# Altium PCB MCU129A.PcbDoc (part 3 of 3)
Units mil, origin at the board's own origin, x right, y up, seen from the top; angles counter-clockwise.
Board outline 3092.79 x 1702.62 mil, 4 copper layers (Top Layer, L2_GND, L3_PWR/SIG, Bottom Layer), stack 58.736 mil thick; 213 components, 108 nets, 914 pads, 219 vias.
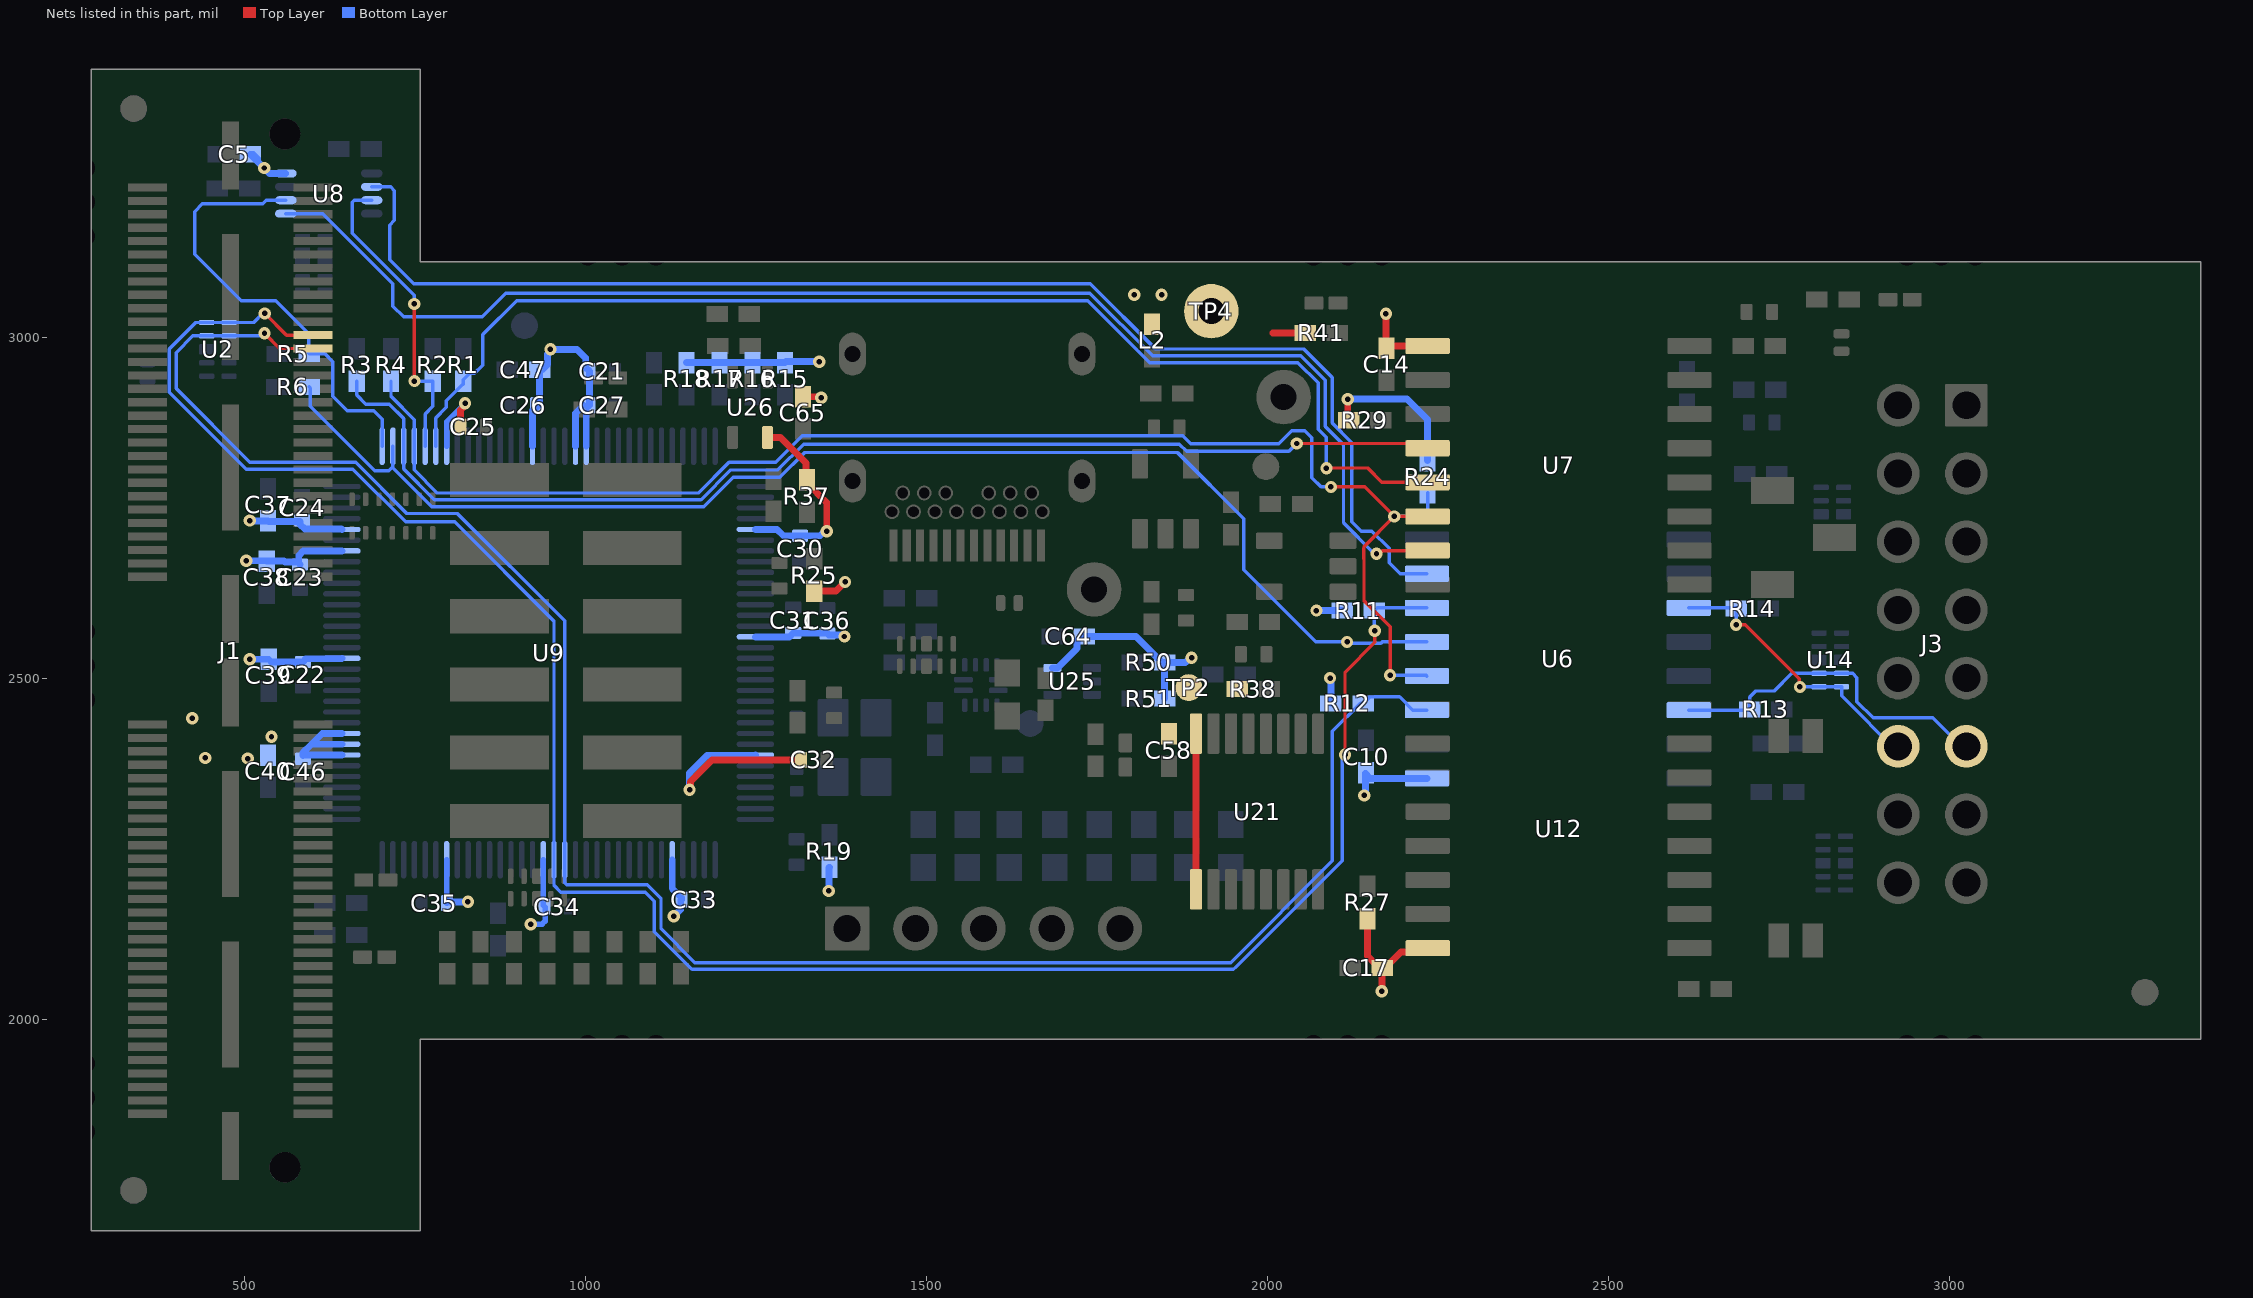
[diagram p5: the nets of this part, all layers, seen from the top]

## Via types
v1: diameter 18, hole 8, Top Layer to Bottom Layer, tented both sides, 219 vias

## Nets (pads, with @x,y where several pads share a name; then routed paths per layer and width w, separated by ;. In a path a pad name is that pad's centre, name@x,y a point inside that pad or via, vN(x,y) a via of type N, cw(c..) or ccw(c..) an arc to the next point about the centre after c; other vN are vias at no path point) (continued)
VCC_3V3: C5.2 C10.1 C14.1 C17.1 C21.2 C22.2 C23.2 C24.2 C25.2 C26.2 C27.2 C30.2 C31.2 C32.2 C33.2 C34.2 C35.2 C36.2 C37.1 C38.1 C39.1 C40.1 C46.2 C47.1 C64.2 C65.2 L2.2 R11.2 R12.2 R15.1 R16.1 R17.1 R18.1 R19.1 R24.2 R25.2 R27.2 R29.2 R37.2 R41.2 R50.2 R51.2 TP4.1 U6.1 U7.1 U8.8 U9.7 U9.8 U9.9 U9.16 U9.26 U9.28 U9.39 U9.47 U9.51 U9.52 U9.69 U9.79 U9.90 U9.101 U9.113 U9.122 U12.16 U25.5 U26.5 | length 3662.8
  Top Layer w10: C25.2@817.13,2869.83 817.13,2894.05 823.61,2900.53 v1(823.61,2904.05) ; v1(1152.82,2337.6) 1154.35,2339.13 1154.35,2349.79 1185.74,2381.18 C32.2@1315.19,2381.18 ; U26.5@1267.02,2854.08 1285.91,2854.08 1323.42,2816.57 1323.42,2793.06 R37.2@1324.81,2791.68 ; C65.2@1318.81,2913.8 1344.19,2913.8 v1(1345.81,2912.18) ; R37.2@1325.3,2787.24 1353.81,2758.74 v1(1353.81,2716.35) ; R25.2@1335.62,2628.69 1367.31,2628.69 v1(1380.81,2642.18) ; 2007.81,3007.18 R41.2@2055.19,3007.18 ; v1(2117.81,2910.18) 2117.81,2880.56 R29.2@2119.19,2879.18 ; R27.2@2146.81,2148.56 2146.81,2093.87 2164.49,2076.18 C17.1@2172.37,2076.18 ; v1(2167.81,2042.18) 2167.81,2075.56 2171.75,2075.56 2195.99,2099.8 2229.57,2099.8 U12.16@2234.94,2105.18 ; v1(2173.81,3035.18) 2173.81,2985.8 2176.19,2988.18 U7.1@2234.88,2988.18
  Bottom Layer w5: 997.25,2901.18 1005.34,2901.18 C27.2@1006.11,2901.18
  Bottom Layer w8: C35.2@796.57,2172.42 U9.122@796.57,2234.88 ; U9.39@796.57,2841.18 796.57,2877.01 v1(823.61,2904.05) ; v1(919.96,2140.3) 936.5,2140.3 941.19,2144.98 C34.2@941.19,2165.18 ; C34.2@938.3,2168.06 U9.113@938.3,2234.88
  Bottom Layer w10: v1(502.81,2673.18) 532.43,2673.18 C38.1@532.81,2672.8 558.19,2672.8 559.81,2671.18 578.26,2671.18 C23.2@579.81,2669.64 ; v1@507.47,2528.18 v1(508.09,2528.8) C39.1@535.81,2528.8 539.73,2524.88 C22.2@585.81,2524.88 590.53,2529.61 642.48,2529.61 U9.16@643.03,2530.16 ; v1(508.09,2732.18) 508.71,2731.56 C37.1@534.81,2731.56 535.81,2730.56 581.81,2730.56 581.81,2726.62 588.62,2719.81 642.35,2719.81 U9.28@643.03,2719.13 ; v1(529.32,3249.06) v1@528.93,3249.06 ; U8.8@560.82,3241.18 536.81,3241.18 v1@528.93,3249.06 ; C23.2@581.81,2667.64 C23.2@579.81,2669.64 ; U9.7@643.03,2388.43 586.67,2388.43 586.05,2387.81 586.05,2391.75 598.48,2404.17 ; U9.8@643.03,2404.17 598.48,2404.17 ; U9.9@643.03,2419.92 614.23,2419.92 598.48,2404.17 ; U9.26@643.03,2687.64 586.26,2687.64 579.81,2681.18 C23.2@579.81,2669.64 ; C35.2@796.57,2172.42 796.81,2172.18 797.81,2173.18 798.31,2172.68 827.31,2172.68 v1(827.81,2173.18) ; U9.47@922.56,2841.18 922.56,2893.37 930.37,2901.18 932.81,2901.18 C47.1@932.81,2953.18 936.75,2953.18 944.56,2960.99 944.56,2976.22 948.81,2980.48 v1(948.81,2983.18) 987.81,2983.18 1000.5,2970.49 1000.5,2956.79 C21.2@1006.11,2951.18 C27.2@1006.11,2901.18 ; U9.51@985.55,2841.18 985.55,2889.48 997.25,2901.18 ; U9.52@1001.3,2841.18 1001.3,2897.13 C27.2@1005.34,2901.18 ; U9.101@1127.28,2234.88 1127.28,2192.96 1141.11,2179.13 C33.2@1141.11,2176.18 1139.81,2174.88 1139.81,2162.1 v1(1129.75,2152.04) ; R18.1@1148.46,2963.8 R17.1@1196.81,2963.8 R16.1@1244.81,2963.8 R15.1@1292.81,2963.8 1294.19,2965.18 v1(1342.81,2965.18) ; v1(1152.82,2337.6) 1152.82,2362.19 1178.24,2387.61 1248.52,2387.61 U9.90@1249.33,2388.43 ; U9.79@1249.33,2561.65 1298.98,2561.65 C31.2@1304.81,2567.48 1305.31,2566.98 1354.31,2566.98 C36.2@1354.81,2566.48 1356.96,2564.33 1377.66,2564.33 v1(1379.81,2562.18) ; U9.69@1249.33,2719.13 1281.18,2719.13 1290.43,2709.88 C30.2@1314.81,2709.88 1343.83,2709.88 1350.29,2716.35 v1(1353.81,2716.35) ; v1(1356.81,2189.18) 1357.31,2189.68 1357.31,2223.44 R19.1@1357.81,2223.94 ; U25.5@1684.67,2516.08 1691.96,2516.08 1720.68,2544.8 1720.68,2555.37 1727.49,2562.18 C64.2@1731.43,2562.18 1807.37,2562.18 1845.37,2524.18 R50.2@1849.3,2524.18 ; R51.2@1849.3,2471.18 R50.2@1849.3,2524.18 ; v1(1888.81,2531.18) 1886.64,2531.18 1879.64,2524.18 R50.2@1849.3,2524.18 ; v1(2071.81,2600.18) R11.2@2109.56,2600.18 ; v1(2091.81,2501.18) 2093.19,2499.8 R12.2@2093.19,2464.18 ; v1(2117.81,2910.18) 2204.81,2910.18 2234.88,2880.11 R24.2@2234.88,2819.99 ; v1(2141.81,2329.18) 2143.81,2331.18 C10.1@2143.81,2360.99 ; C10.1@2143.81,2361.56 C10.1@2143.81,2360.99 ; U6.1@2233.88,2354.18 2150.62,2354.18 C10.1@2143.81,2360.99 ; C5.2@519.56,3258.43 C5.2@508.81,3269.18 512.75,3269.18 519.56,3262.37 C5.2@519.56,3258.43 ; C5.2@519.56,3258.43 v1@528.93,3249.06
  other v1: 504.81,2383.18 442.81,2384.18 539.81,2415.18 423.81,2442.18 1804.81,3063.18 1844.81,3063.18
VREF: C58.2 R38.1 TP2.1 U21.8 U21.9 | length 228.3
  Top Layer w10: U21.9@1895.3,2191.39 U21.8@1895.3,2419.74
XDS_EEPROM_SCL: J1.23 R11.1 U2.5 U2.6 U6.6 U9.112 | length 3163.7
  Top Layer w5: v1(529.98,3035.86) 561.79,3004.05 J1.23@600.99,3004.05 ; v1(2113.81,2388.68) 2113.81,2509.88 2157.4,2553.47 v1(2157.4,2570.66)
  Bottom Layer w5: v1(529.98,3035.86) 527.05,3035.86 513.75,3022.56 U2.6@477.69,3022.56 U2.5@444.81,3022.56 428.81,3022.56 389.98,2983.73 389.98,2920.33 502.75,2807.56 659.08,2807.56 736.42,2730.22 808.41,2730.22 954.05,2584.58 U9.112@954.05,2234.88 954.05,2197.14 963.93,2187.26 1082.57,2187.26 1082.82,2187.02 1087.7,2187.02 1100.94,2173.78 1100.94,2129.47 1153.17,2077.24 1156.31,2074.1 1950.17,2074.1 1953.31,2077.24 2109.6,2233.52 2109.6,2384.47 v1(2113.81,2388.68) ; v1(2157.4,2570.66) 2156.81,2571.24 R11.1@2156.81,2600.18 2160.81,2604.18 U6.6@2233.88,2604.18
XDS_EEPROM_SCL_ISO: J3.12 R14.1 U6.11 U14.5 U14.6 | length 423
  Top Layer w5: v1(2687.19,2579.56) 2700.72,2579.56 2779.79,2500.5 2779.79,2489.2 v1(2780.81,2488.18)
  Bottom Layer w5: U6.11@2617.74,2604.18 R14.1@2687.19,2604.18 ; v1(2687.19,2579.56) R14.1@2687.19,2603.18 ; v1(2780.81,2488.18) 2781.07,2488.44 U14.6@2808.93,2488.44 U14.5@2841.81,2488.44 2841.81,2475.04 J3.12@2924.81,2392.04
XDS_EEPROM_SDA: J1.25 R12.1 U2.4 U2.7 U6.3 U9.111 | length 2988.8
  Top Layer w5: v1(529.55,3006.81) 551.99,2984.36 J1.25@600.99,2984.36
  Bottom Layer w5: v1(529.55,3006.81) 525.61,3002.87 U2.7@477.69,3002.87 U2.4@444.81,3002.87 424.46,3002.87 399.98,2978.39 399.98,2925.76 508.18,2817.56 663.22,2817.56 738.27,2742.51 812.46,2742.51 969.8,2585.17 969.8,2200.99 972.73,2198.06 1090.8,2198.06 1110.94,2177.92 1110.94,2133.61 1160.45,2084.1 1946.03,2084.1 2095.31,2233.38 2095.31,2423 2136.49,2464.18 R12.1@2140.43,2464.18 2149.74,2473.49 2156.42,2473.49 2156.61,2473.68 2193.71,2473.68 2213.21,2454.18 U6.3@2233.88,2454.18
XDS_EEPROM_SDA_ISO: J3.11 R13.1 U6.14 U14.4 U14.7 | length 509.1
  Bottom Layer w5: U6.14@2617.74,2454.18 R13.1@2707.19,2454.18 ; R13.1@2707.19,2455.18 2707.19,2473.46 2715.99,2482.27 2742.84,2482.27 2768.7,2508.13 U14.7@2808.93,2508.13 2858.14,2508.13 2864.3,2501.97 2864.3,2466.69 2888.01,2442.98 2975.2,2442.98 J3.11@3025.65,2392.53
XDS_RXD: R5.1 U8.6 U9.33 | length 663.9
  Bottom Layer w5: 522.3,3054.34 495.53,3054.34 427.31,3122.56 427.31,3185.2 438.56,3196.45 526.93,3196.45 532.3,3201.81 U8.6@560.82,3201.81 ; 522.32,3054.36 537.64,3054.36 ; 537.66,3054.34 545.8,3054.34 594.33,3005.82 594.33,2977.4 R5.1@595.25,2976.48 618.24,2976.48 629.43,2965.29 629.43,2914.42 650.88,2892.97 689.7,2892.97 702.08,2880.59 U9.33@702.08,2841.18
XDS_RXD_BUF: U6.7 U8.2 | length 1970.6
  Bottom Layer w5: U8.2@686.81,3221.5 714.56,3221.5 720.06,3216 720.06,3172.4 712.93,3165.27 712.93,3114.61 748.39,3079.15 1740.42,3079.15 1835.89,2983.68 2053.01,2983.68 2094.77,2941.93 2094.77,2875.15 2123.78,2846.14 2123.78,2730.5 2137.67,2716.61 2153.07,2716.61 2178.42,2691.26 2178.42,2670.39 2194.64,2654.18 U6.7@2233.88,2654.18
XDS_TCK: R3.2 U7.4 U9.35 | length 1743.4
  Top Layer w5: v1(2043.11,2845.11) 2227.95,2845.11 U7.4@2234.88,2838.18
  Bottom Layer w5: R3.2@664.81,2936.69 664.81,2916.25 678.08,2902.97 712.35,2902.97 733.58,2881.74 U9.35@733.58,2841.18 ; U9.35@733.53,2841.13 733.53,2807.74 778.75,2762.51 1169.59,2762.51 1213.41,2806.33 1282.04,2806.33 1320,2844.29 1871,2844.29 1881.6,2833.7 2031.69,2833.7 2033.63,2835.64 v1(2043.11,2845.11)
XDS_TDI: R1.1 U7.5 U9.38 | length 1778.5
  Top Layer w5: v1(2086.52,2808.71) 2087.03,2809.22 2146.9,2809.22 2167.93,2788.18 U7.5@2234.88,2788.18
  Bottom Layer w5: U9.38@780.82,2841.18 780.82,2882.54 796.28,2898 796.28,2908 R1.1@819.73,2931.45 ; R1.1@821.04,2931.7 821.04,2938.65 830.35,2947.97 837.42,2947.97 849.5,2960.04 849.5,3004.94 899.1,3054.54 1736.75,3054.54 1827.61,2963.68 2044.73,2963.68 2074.31,2934.1 2074.31,2866.13 2086.44,2854 2086.44,2808.8 v1(2086.52,2808.71)
XDS_TDO: R2.1 U8.3 U9.37 | length 456.7
  Top Layer w5: v1(749.04,3049.71) 749.33,3049.42 v1(749.33,2936.69)
  Bottom Layer w5: U8.3@686.81,3201.81 661.23,3201.81 658.3,3198.88 658.3,3153.21 749.04,3062.47 v1(749.04,3049.71) ; v1(749.33,2936.69) R2.1@776.23,2936.7 776.23,2899.52 765.08,2888.36 U9.37@765.08,2841.18
XDS_TDO_BUF: U7.7 U8.5 | length 2036.4
  Top Layer w5: v1(2159.92,2683.6) 2163.44,2683.6 2168.02,2688.18 U7.7@2233.88,2688.18
  Bottom Layer w5: U8.5@560.82,3182.13 615.24,3182.13 717.83,3079.54 717.83,3046.53 733.44,3030.92 848.65,3030.92 883.33,3065.61 1739.83,3065.61 1831.75,2973.68 2048.87,2973.68 2084.55,2938 2084.55,2870.03 2111.61,2842.97 2111.61,2728.53 2156.54,2683.6 v1(2159.92,2683.6)
XDS_TMS: R4.2 R24.1 U6.4 U7.6 U9.36 | length 2178.2
  Top Layer w5: v1(2093.11,2781.49) 2142.5,2781.49 v1(2185.81,2738.18) ; v1(2179.81,2505.18) 2179.81,2576.41 2141.58,2614.64 2141.58,2675.78 2141.42,2675.94 2141.42,2691.26 2141.58,2691.42 2141.58,2693.96 v1(2185.81,2738.18) ; U7.6@2234.88,2738.18 v1(2185.81,2738.18)
  Bottom Layer w5: R4.2@715.05,2936.69 715.05,2914.42 749.33,2880.14 U9.36@749.33,2841.18 748.97,2840.82 748.97,2806.44 782.9,2772.51 1165.45,2772.51 1210.57,2817.63 1279.19,2817.63 1318,2856.43 1875.59,2856.43 1887.53,2844.49 2016.33,2844.49 2035.44,2863.61 2054.93,2863.61 2065.04,2853.5 2065.04,2794.98 2078.53,2781.49 v1(2093.11,2781.49) ; v1(2179.81,2505.18) 2232.88,2505.18 U6.4@2233.88,2504.18 ; v1(2185.81,2738.18) 2225.18,2738.18 2234.88,2747.88 R24.1@2234.88,2772.75
XDS_TXD: R6.1 U6.5 U9.34 | length 1956.5
  Bottom Layer w5: R6.1@594.96,2928.08 596.56,2926.48 596.56,2899.94 691.38,2805.12 711.59,2805.12 717.83,2811.36 U9.34@717.83,2841.18 ; 717.03,2810.56 717.03,2810.09 774.61,2752.51 1173.73,2752.51 1216.64,2795.42 1285.27,2795.42 1321.83,2831.98 1868.17,2831.98 1965.03,2735.12 1965.03,2660.17 2071.01,2554.18 v1(2116.81,2554.18) 2118.83,2552.16 2166.59,2552.16 2168.62,2554.18 U6.5@2233.88,2554.18
pads on no net: Designator1_1_2_2. Designator1_1_2_2_1. Designator1_1_2_3. Designator1_1_2_3_1. Designator1_1_2_4. Designator1_1_2_5. Designator1_1_2_5_1. Designator1_1_2_7. Designator1_1_2_7_1. Designator1_1_2_8. Designator1_1_2_8_1. Designator1_3_1_1. Designator1_3_1_1_1. Designator1_3_1_1_2. Designator2_1. Designator2_1_1. Designator3_1_2_2. Designator3_1_2_2_1. Designator3_1_2_3. Designator3_1_2_3_1. Designator3_1_2_4. Designator3_3_1_1. Designator3_3_1_1_1. Designator3_3_1_1_2. Designator4_1_2_2. Designator4_1_2_2_1. Designator4_1_2_3. Designator4_1_2_3_1. Designator4_1_2_4. Designator4_3_1_1. Designator4_3_1_1_1. Designator4_3_1_1_2. Designator5_1. Designator5_1_1. Designator6_1. Designator6_1_1. FID1.1 FID2.1 FID3.1 FID5.1 FID6.1 FID7.1 FID8.1 FID9.1 FID10.1 FID11.1 FID12.1 FID13.1 FID14.1 FID15.1 J1.1 J1.2 J1.3 J1.4 J1.6 J1.8 J1.10 J1.12 J1.14 J1.16 J1.27 J1.29 J1.30 J1.32 J1.34 J1.35 J1.36 J1.37 J1.38 J1.39 J1.40 J1.41 J1.42 J1.43 J1.44 J1.45 J1.46 J1.47 J1.48 J1.49 J1.50 J1.51 J1.52 J1.53 J1.54 J1.55 J1.56 J1.57 J1.58 J1.59 J1.60 J1.61 J1.62 J1.63 J1.64 J1.65 J1.66 J1.67 J1.68 J1.69 J1.70 J1.71 J1.72 J1.73 J1.74 J1.75 J1.76 J1.79 J1.80 J1.81 J1.82 J1.83 J1.84 J1.85 J1.86 J1.87 J1.88 J1.89 J1.90 J1.91 J1.92 J1.93 J1.94 J1.95 J1.96 J1.97 J1.98 J1.99 J1.100 J1.101 J1.102 J1.103 J1.104 J1.105 J1.106 J1.107 J1.108 J1.109 J1.110 J1.111 J1.112 J1.113 J1.114 J1.115 J1.116 J1.MH1 J1.MH2 J3.8 J5.A2 J5.A3 J5.A8 J5.A10 J5.A11 J5.B2 J5.B3 J5.B8 J5.B10 J5.B11 LBL1.0 U1.3@585.43,3109.19 U1.8@618.31,3109.19 U2.3@444.81,2983.19 U2.8@477.69,2983.19 U3.1S U3.2S U4.3@929.81,2210.62 U4.8@929.81,2177.74 U9.1 U9.2 U9.5 U9.6 U9.11 U9.12 U9.13 U9.14 U9.15 U9.18 U9.19 U9.20 U9.21 U9.22 U9.23 U9.24 U9.25 U9.27 U9.29 U9.30 U9.31 U9.32 U9.41 U9.42 U9.43 U9.44 U9.45 U9.46 U9.49 U9.50 U9.53 U9.54 U9.56 U9.57 U9.65 U9.67 U9.71 U9.72 U9.73 U9.74 U9.75 U9.76 U9.77 U9.78 U9.81 U9.82 U9.83 U9.84 U9.85 U9.86 U9.91 U9.92 U9.95 U9.97 U9.98 U9.99 U9.100 U9.102 U9.103 U9.104 U9.105 U9.106 U9.107 U9.108 U9.109 U9.110 U9.116 U9.117 U9.118 U9.119 U9.120 U9.121 U9.123 U9.124 U9.125 U9.126 U9.127 U9.128 U13.3@2811.93,2741.5 U13.8@2844.81,2741.5 U14.3@2841.81,2527.81 U14.8@2808.93,2527.81 U17.1S U17.2S U18.3@2814.81,2229.87 U18.8@2847.68,2229.87 U20.1 U21.11 U21.12 U21.13 U21.14 U22.1S U22.2S U23.5 U24.3@1500.22,2551.47 U24.8@1500.22,2518.59 U26.1

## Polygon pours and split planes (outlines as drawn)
GNDH on Top Layer "NONET_L-01_P-001" (solid, remove dead copper, pour order 3): 2598.27,1971.84 2598.27,3111.85 3359.48,3111.85 3359.48,1971.84
GND on Top Layer "NONET_L-01_P-001" (solid, remove dead copper, pour order 12): 2257.58,1971.84 2257.58,3111.85 757.95,3111.85 757.95,3393.8 275.59,3393.8 275.59,1691.18 757.95,1691.18 757.95,1971.84
GND on Top Layer "Top Layer-GND" (solid, pour order 10): 1817.81,2541.18 1819.81,2539.18 1923.25,2539.18 1940.06,2522.37 1971.56,2522.37 1971.56,2596.43 1818.18,2596.43 1818.18,2541.55
NetC50_1 on Top Layer "NONET_L-01_P-001" (solid, pour order 9): 1982.99,2638.41 1982.99,2617.15 1987.3,2612.83 1987.3,2473.37 2018.8,2473.37 2018.8,2613.59 2022.36,2617.15 2022.36,2638.41 2021.18,2639.59 1984.17,2639.59
GND on Top Layer "NONET_L-01_P-001" (solid, pour order 6): 1861.36,2940.33 1860.81,2939.78 1860.81,2802.76 1875.75,2787.82 1913.45,2787.82 1945.81,2820.18 1945.81,2941.18 1933.81,2953.18 1873.79,2953.18 1860.94,2940.33
NetC54_2 on Top Layer "NONET_L-01_P-001" (solid, pour order 5): 1769.06,2786.18 1837.06,2786.18 1844.56,2793.68 1844.56,2988.31 1766.19,2988.31 1762.06,2984.18 1762.06,2794.18 1768.06,2788.18
+5V0 on Top Layer "NONET_L-01_P-001" (solid, pour order 1): 1596.23,2745.1 1603.12,2738.21 1603.12,2664.65 1590.31,2651.83 1590.31,2490.68 1595.56,2485.43 1765.06,2485.43 1792.81,2513.18 1792.81,2599.18 1805.81,2612.18 1936.81,2612.18 1968.46,2643.84 1968.46,2723.69 1964.97,2727.18 1905.73,2727.18 1886.73,2746.18 1874.81,2746.18 1874.81,2693.53 1876.59,2691.75 1864.01,2679.18 1836.81,2679.18 1829.15,2686.84 1829.15,2728.13 1815.1,2742.18 1711.62,2742.18 1705.81,2736.37 1705.81,2669.71 1652.28,2616.18 1625.81,2616.18 1619,2622.99 1619,2661.1 1614.94,2665.16 1614.94,2731.74 1619.83,2736.64 1619.83,2747.64 1611.55,2755.93 1602.58,2755.93 1596.23,2749.59 1596.23,2740.62 1603.12,2733.73 1603.12,2732.85
VREF on Top Layer "NONET_L-01_P-001" (solid, pour order 11): 1927.41,2509.64 1879.24,2509.64 1854.62,2485.02 1843.86,2474.26 1843.86,2403.61 1874.19,2403.61 1887.59,2390.21 1903.02,2390.21 1904.16,2391.35 1904.16,2463.92 1913.61,2473.37 1971.56,2473.37 1971.56,2496.99 1940.06,2496.99
+5V0_A on Top Layer "NONET_L-01_P-001" (solid, pour order 8): 1904.81,2761.18 1963.81,2820.18 1963.81,2827.18 1974.81,2838.18 2018.81,2838.18 2022.81,2834.18 2022.81,2735.18 2043.6,2714.39 2129.45,2714.39 2130.63,2713.22 2130.63,2691.95 2129.45,2690.77 1982.99,2690.77 1982.99,2730 1969.93,2743.06 1904.81,2743.06
VCC_3V3 on Top Layer "NONET_L-01_P-001" (solid, pour order 7): 1855.93,3004.06 1883.81,2976.18 1999.81,2976.18 2018.81,2995.18 2018.81,3079.18 2001.81,3096.18 1870.81,3096.18 1860.81,3086.18 1797.81,3086.18 1788.81,3077.18 1788.81,3023.18 1807.93,3004.06
GND on Top Layer "NONET_L-01_P-001" (solid, pour order 4): 1579.81,2469.18 1690.51,2469.18 1702.91,2456.78 1702.91,2368.29 1692.81,2358.18 1590.81,2358.18 1568.81,2380.18 1568.81,2458.18 1578.81,2468.18
+5V0 on Top Layer "NONET_L-01_P-001" (solid, pour order 2): 293.81,3082.18 293.81,3115.18 300.81,3122.18 319.06,3122.18 323.45,3117.79 323.45,3083.54 323.45,3069.11 380.89,3069.11 394.81,3083.03 394.81,3109.18 419.96,3109.18 420.46,3108.68 442,3108.68 442,3037.42 397.42,3037.42 397.1,3037.74 380.86,3037.74 380.54,3037.42 328.7,3037.42 326.42,3039.69 305.3,3039.69 293.81,3051.18
VCC_3V3 on Top Layer "NONET_L-01_P-001" (solid, pour order 0): 1394.81,2532.18 1394.81,2589.18 1391.81,2592.18 1391.81,2655.18 1324.81,2655.18 1321.81,2652.18 1323.81,2660.18 1314.81,2651.18 1314.81,2550.18 1332.81,2532.18
GNDH on L2_GND "NONET_L-01_P-001" (solid, remove dead copper, pour order 13): 2585.01,1971.84 2585.01,3111.84 3367.6,3111.84 3367.6,1971.84
GND on L2_GND "NONET_L-01_P-001" (solid, remove dead copper, pour order 14): 2270.05,1971.84 2270.05,3111.85 757.17,3111.85 757.17,3393.8 274.81,3393.8 274.81,1691.18 757.17,1691.18 757.17,1971.84
+5V0 on L3_PWR/SIG "NONET_L-01_P-001" (solid, remove dead copper, pour order 15): 1438.75,2661.62 1403.81,2626.67 1402.3,2626.67 1380.81,2605.18 1334.21,2605.18 1291.42,2647.97 1291.42,2761.57 1281.68,2771.31 1171.98,2881.01 1077.81,2881.01 1028.23,2930.59 912.74,2930.59 863.15,2881.01 726.98,2881.01 493.81,3114.18 294.81,3114.18 294.81,2667.18 575.81,2386.18 1867.81,2386.18 1867.81,2615.18 1811.81,2671.18 1652.81,2671.18 1634.62,2689.37 1634.62,2726.35 1630.68,2726.35 1619.73,2737.3 1619.73,2751.35 1615.15,2755.93 1602.58,2755.93 1595.25,2748.6 1595.25,2708.24 1528.32,2708.24 1528.32,2734.22 1526.26,2736.28 1526.26,2752.15 1516.63,2761.78 1509.36,2761.78 1494,2746.42 1494,2692.58 1463.04,2661.62
VCC_3V3 on L3_PWR/SIG "NONET_L-01_P-001" (solid, remove dead copper, pour order 17): 757.17,3393.8 757.17,3111.85 2270.25,3111.85 2276.2,3105.89 2276.2,1983.76 445.23,1983.76 274.81,2154.18 274.81,3393.8
IO_TGT_V_FL on L3_PWR/SIG "NONET_L-01_P-001" (solid, remove dead copper, pour order 16): 2663.81,3096.18 2777.81,3096.18 2849.81,3024.18 2849.81,2420.18 2849.81,2061.18 2782.81,1994.18 2610.81,1994.18 2589.81,2015.18 2589.81,3047.18 2638.81,3096.18
GND on Bottom Layer "NONET_L-01_P-001" (solid, remove dead copper, pour order 22): 2270.83,1971.84 2270.83,3111.85 757.95,3111.85 757.95,3393.8 275.59,3393.8 275.59,1691.18 757.95,1691.18 757.95,1971.84
VCC_3V3 on Bottom Layer "NONET_L-01_P-001" (solid, pour order 20): 429.81,2757.18 513.12,2757.18 523,2747.31 521.81,2746.12 521.81,2596.18 516.81,2591.18 516.81,2509.18 484.81,2477.18 484.81,2441.18 502.81,2423.18 557.81,2423.18 557.81,2387.56 534.81,2364.56 534.19,2365.18 434.81,2365.18 406.81,2393.18 406.81,2734.18 426.81,2754.18
VCC_3V3 on Bottom Layer "NONET_L-01_P-001" (solid, pour order 19): 670.59,2419.92 670.59,2426.97 530.59,2426.97 511.81,2408.18 511.81,2370.18 514.81,2367.18 592.98,2367.18 610.29,2384.49 666.65,2384.49 670.59,2388.43
+5V0 on Bottom Layer "NONET_L-01_P-001" (solid, pour order 18): 1591.81,2752.76 1591.81,2570.18 1600.81,2561.18 1646.81,2561.18 1684.81,2599.18 1684.81,2730.35 1662.4,2752.76

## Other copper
Top Layer:
  text ".Layer_Name" at 596.92,-407.66 h60
L2_GND:
  text ".Layer_Name" at 596.92,-432.66 h60
L3_PWR/SIG:
  text ".Layer_Name" at 596.92,-432.66 h60
Bottom Layer:
  text ".Layer_Name" at 596.92,-432.66 h60

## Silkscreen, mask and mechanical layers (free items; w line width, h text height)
Top Overlay:
  circle w9.84: c2553.19,2056.79 r4.92
  circle w19.68: c2529.81,2116.18 r9.84
  lines w6: 2292.33,2080.28 2292.33,2493.66 2567.92,2493.66 2567.92,2080.28 2292.33,2080.28
  text "3V3" at 2153.81,3068.18 h25
  text "ISOLATED" at 3039.81,3041.18 h60
  text "IO_TGT_V" at 2994.81,2991.18 h25
  text "+5V0 LED" at 845.81,2979.18 h25
  text "GNDH" at 2899.81,2946.18 h25
  text "cJTAG" at 2666.55,2845.97 h60
  text "GND" at 686.75,2794.09 h25
  text "GND" at 1153.81,2760.18 h25
  text "Mode" at 2696.81,2665.18 h60 r90
  text "J1.11" at 1150.81,2664.18 h25
  text "J1.5" at 696.28,2653.99 h25
  text "J1.13" at 1161.72,2561.84 h25
  text "J1.7" at 699.81,2551.18 h25
  text "JTAG" at 2708.44,2525.3 h60
  text "VREF" at 1764.81,2511.18 h25
  text "J1.9" at 697.81,2474.18 h25
  text "J1.15" at 1159.81,2467.18 h25
  text "OFF" at 2760.81,2459.18 h60
  text "J1.118" at 652.81,2380.18 h25
  text "J1.117" at 1149.81,2376.18 h25
  text "J1.120" at 649.81,2278.18 h25
  text "J1.119" at 1155.81,2278.18 h25
  text "GND" at 1743.81,2192.18 h25
  text "VOUTA" at 1388.81,2179.18 h25 r90
  text "VOUTB" at 1491.81,2179.18 h25 r90
  text "VOUTC" at 1586.81,2179.18 h25 r90
  text "VOUTD" at 1690.81,2179.18 h25 r90
  text "ON" at 2874.81,2101.18 h60
  text "RXD" at 2759.81,2001.18 h25 r90
  text "NON-ISOLATED" at 1848.81,1993.18 h60
  text "POCI" at 2819.81,1991.18 h25 r90
  text ".Layer_Name" at 596.92,-407.66 h60
Bottom Overlay:
  lines w5: 3180.1,2376.02 3330,2376.02 ; 3330,2228.18 3180,2228.18 3180,2878.18 3330,2878.18
  text "ISOLATED" at 3109.56,3053.94 h60
  text "3V3" at 1841.81,3030.18 h50
  text "GNDH" at 2959.81,2946.18 h40
  text "IO_TGT_V" at 3154.81,2946.18 h40
  text "GND" at 2069.91,2821.37 h50
  text "TCK" at 2864.81,2816.18 h40
  text "TMS" at 3145,2785 h40
  text "TDI" at 3130,2685 h40
  text "TDO" at 2869.81,2646.18 h40
  text "5V0" at 1898.81,2614.18 h60
  text "GNDH" at 3170,2585 h40
  text "RXD" at 3140,2485 h40
  text "TXD" at 2878.39,2431.74 h40
  text "SDA" at 3140,2395 h40
  text "SCL" at 2878.24,2387.02 h40
  text "PICO" at 2888.9,2294.76 h40
  text "CLK" at 3145,2290 h40
  text "SL#" at 3245,2250 h70 r270
  text "POCI" at 3155,2185 h40
  text "XDS110ISO-EVM" at 2592.81,2158.99 h60
  text "STE" at 2954.81,2131.18 h40
  text "GND" at 1931.22,2114.78 h50
  text "MCU129A" at 2467.95,2099.22 h60
  text "ASSY#" at 2012.4,2047.74 h60
  text "not FCC approved for resale." at 3032.81,1993.18 h60
  text "NON-ISOLATED" at 2249.81,1986.18 h60
  text ".Layer_Name" at 596.92,-407.66 h60
Top Paste:
  text ".Layer_Name" at 596.92,-407.66 h60
Bottom Paste:
  text ".Layer_Name" at 596.92,-407.66 h60
Top Solder:
  text ".Layer_Name" at 594.59,-414.16 h60
Bottom Solder:
  text ".Layer_Name" at 599.59,-414.16 h60
M1 Board Outline:
  lines w3: 0,477.51 0,6303.72 0,6500.57 196.85,6500.57 836.69,6500.57 4238.97,6500.57 4238.97,6010.2 ; 0,489.54 0,0 3402.28,0 4042.12,0 4238.97,0 4238.97,196.85 4238.97,6023.06 ; 870.59,6021.77 3368.38,6021.77 ; 870.59,1774.99 3368.38,1774.99 ; 870.59,1774.99 3368.38,1774.99 ; 870.59,1775 870.59,1893.11 ; 870.59,1893.11 3368.38,1893.11 ; 870.59,1893.11 3368.38,1893.11 ; 870.59,3190.58 3368.38,3190.58 ; 870.59,3190.58 3368.38,3190.58 ; 870.59,3190.59 870.59,3308.7 ; 870.59,3308.7 3368.38,3308.7 ; 870.59,3308.7 3368.38,3308.7 ; 3368.38,1775 3368.38,1893.11 ; 3368.38,3190.59 3368.38,3308.7 ; 3368.38,6021.77 836.69,6021.77 836.69,6303.72 196.85,6303.72 196.85,477.51 1103.09,477.51 3402.28,477.51 3402.28,196.85 4042.12,196.85 4042.12,6021.77 3368.38,6021.77 ; 275.59,1691.18 757.95,1691.18 757.95,1971.84 3368.38,1971.84 3368.38,3111.85 757.95,3111.85 757.95,3393.8 275.59,3393.8 275.59,1691.18 ; 275.59,4522.36 757.95,4522.36 757.95,4803.03 3368.38,4803.03 3368.38,5943.03 757.95,5943.03 757.95,6224.98 275.59,6224.98 275.59,4522.36 ; 870.59,556.25 3481.02,556.25 3481.02,275.59 3963.38,275.59 3963.38,1978.21 3481.02,1978.21 3481.02,1696.25 870.59,1696.25 870.59,556.25 ; 870.59,3387.44 870.59,4527.44 3481.02,4527.44 3481.02,4809.39 3963.38,4809.39 3963.38,3106.77 3481.02,3106.77 3481.02,3387.44 870.59,3387.44 ; 870.59,4606.18 3368.38,4606.18 3368.38,4724.29 870.59,4724.29 870.59,4606.18
  text ".Layer_Name" at 614.81,-323.82 h60
M2 Board Dimensions:
  text ".Layer_Name" at 596.92,-407.66 h60
M10 Fab Notes:
  drawing of 243 lines, arcs and shapes, not listed
  text "3" at 5752.35,8522.96 h70
  text "4" at 8259.02,8522.96 h70
  text "5" at 10758.01,8522.96 h70
  text "6" at 13263.01,8522.96 h70
  text "A" at -388.99,7379.96 h70
  text "DESIGN INFORMATION" at 12409.53,6842.64 h60
  text "4" at 12804.01,6713.25 h60
  text "MIN. TRACK WIDTH:" at 11764.97,6710.51 h60
  text "MIL" at 13015.97,6710.51 h60
  text "5" at 12801.46,6593.86 h60
  text "MIN. CLEARANCE:" at 11764.97,6586.39 h60
  text "MIL" at 13015.97,6586.39 h60
  text "MIN. VIA PAD SIZE:" at 11764.97,6462.26 h60
  text "18" at 12787.66,6454.89 h60
  text "MIL" at 13038.51,6453.46 h60
  text "EXTERNAL" at 13286.11,6334.95 h60
  text "0.127mm (5.0MIL)" at 12459.97,6332.36 h60
  text "MINIMUM ANNULAR RING" at 11435.74,6324.14 h60
  text "PER" at 11635.74,6214.01 h60
  text "IPC-D-275 CLASS 2 LEVEL C" at 11855.74,6214.01 h60
  text "MIL, HOLES" at 13343.97,6113.53 h60
  text "+/-" at 12951.51,6104.95 h60
  text "+/-" at 13805.51,6104.95 h60
  text "REGISTRATION TOLERANCES:" at 11435.74,6103.88 h60
  text "METAL" at 12635.51,6103.88 h60
  text "5" at 13211.71,6103.89 h60
  text "3" at 14044.71,6103.89 h60
  text "MIL" at 14160.97,6103.88 h60
  text "HOLE SIZE TOLERANCE (UNLESS OTHERWISE SPECIFIED):" at 11435.74,6005.57 h60
  text "+/-" at 13805.51,6002.7 h60
  text "3" at 14044.71,6001.63 h60
  text "MIL" at 14160.97,6001.63 h60
  text "MATERIAL:" at 11360.97,5863.98 h60
  text "FR-4 High Tg" at 12347.41,5735.46 h60
  text "FR-408" at 11781.97,5722.95 h60
  text "OTHER" at 13269.97,5722.95 h60
  text "X" at 12208.2,5722.16 h60
  text "X" at 13260.51,5582.47 h60
  text "62 MIL (1.6mm) +/-10%" at 12102.07,5579.92 h60
  text "61 MIL +/-10%" at 13682.51,5573.46 h45
  text "THICKNESS:" at 11435.74,5571.7 h60
  text "OTHER" at 13386.97,5571.7 h60
  text "TOLERANCE:" at 11435.74,5433.39 h60
  text "X" at 12283.97,5433.39 h60
  text "ANSI IPC-6012 TYPE 3 CLASS 2" at 12461.99,5433.39 h60
  text "OTHER +/-" at 12461.97,5289.2 h60
  text "BOW & TWIST:" at 11435.74,5144.01 h60
  text "X" at 12283.97,5144.01 h60
  text "ANSI IPC-6012 TYPE 3 CLASS 2" at 12461.99,5144.01 h60
  text "B" at -388.99,4999.96 h70
  text "B" at 14411.01,4999.96 h70
  text "OTHER +/-" at 12461.97,4997.31 h60
  text "DRILLING:" at 11360.97,4866.69 h60
  text "NC_DRILL FILES" at 13121.97,4761.51 h60
  text "REFERENCE:" at 11435.74,4757.57 h60
  text "X" at 12092.97,4757.47 h60
  text "AS SHOWN" at 12270.97,4757.57 h60
  text "X" at 12993.97,4757.57 h60
  text "OTHER" at 13419.97,4615.32 h60
  text "PTH COPPER THICKNESS:" at 11435.42,4611.79 h60
  text "X" at 12574.65,4611.79 h60
  text "20-30 um" at 12702.65,4611.79 h60
  text "BOARD FINISH:" at 11360.97,4464.19 h60
  text "SILKSCREEN:" at 11516.19,4354.06 h60
  text "X" at 12473.97,4354.06 h60
  text "TOP" at 12590.97,4354.06 h60
  text "X" at 12983.97,4354.06 h60
  text "BOTTOM" at 13101.97,4354.06 h60
  text "SILKSCREEN COLOR:" at 11516.19,4198.88 h60
  text "X" at 12472.97,4198.88 h60
  text "WHITE" at 12590.97,4198.88 h60
  text "OTHER" at 13101.97,4198.88 h60
  text "X" at 12593.15,4055.22 h60
  text "GREEN" at 12721.97,4055.43 h60
  text "OTHER" at 13339.97,4055.43 h60
  text "SOLDER RESIST COLOR:" at 11516.19,4048.56 h60
  text "MATTE" at 12721.97,3901.17 h60
  text "SEMI-GLOSS" at 13339.51,3900.54 h60
  text "X" at 13195.57,3898.48 h60
  text "IMMERSION GOLD (ENIG)" at 12421.97,3728.4 h60
  text "X" at 12242.51,3722.1 h60
  text "ENEPIG" at 13759.51,3721.18 h60
  text "SURFACE FINISH:" at 11360.97,3720.18 h60
  text "SCALE : NTS" at 5801.96,3682.18 h80
  text "NOTES:" at 4609.15,3595.59 h60
  text "IMM. TIN/SILVER OR EQUIV" at 11690.51,3582.87 h60
  text "OTHER" at 13121.97,3578.93 h60
  text "1. BOARD SHALL MEET THE REQUIREMENTS OF UL-796E WITH FLAMMABILITY RATING OF MINIMUM 94V-0. UL LOGO," at 4635.9,3449.77 h60
  text "ARRAY/PANEL:" at 11360.97,3423.55 h60
  text "CUT AND TRIM PER M1 BOARD OUTLINE" at 12421.97,3415.33 h60
  text "X" at 12241.78,3412.26 h60
  text "MANUFACTURER'S IDENTIFICATION AND DATE CODE LETTER SHALL BE RENDERED IN SILKSCREEN." at 4742.63,3350.77 h60
  text "N.C. ROUTE" at 12421.97,3279.36 h60
  text "V. SCORE" at 13287.97,3279.36 h60
  text "2. VENDOR MAY ADJUST SOLDERMASK WHEREVER SOLDERMASK PADS ARE THE SAME SIZE (1:1) AS PER THE MANUFACTURING CAPABILITIES" at 4628.91,3224.99 h60
  text "CERTIFICATION:" at 11360.97,3150.24 h60
  text "MATERIALS AND WORKMANSHIP FOR ALL PCBS" at 12085.97,3150.24 h60
  text "AND ALL OTHER SOLDER MASK PADS SHALL NOT BE MODIFIED, PROVIDED NO ADJACENT COPPER IS EXPOSED AND NO CONFLICT IS PRODUCED" at 4735.64,3125.99 h60
  text "TO MEET OR EXCEED THE REQUIREMENTS OF:" at 12085.97,3056.17 h60
  text "WITH ANY STATED \"VIA TENTING/COVERING\" REQUIREMENTS." at 4735.64,3032.71 h60
  text "X" at 11723.48,2927.54 h60
  text "ANSI IPC-A-600F CLASS ->" at 11851.47,2927.54 h60
  text "X" at 13499.48,2927.54 h60
  text "2" at 13609.47,2927.54 h60
  text "1" at 13294.47,2926.05 h60
  text "3" at 13963.47,2926.05 h60
  text "3. MANUFACTURER'S IDENTIFICATION,DATECODE LETTER SHALL BE SILKSCREENED ON SOLDER SIDE OF THE BOARD." at 4632.59,2914.61 h60
  text "X" at 12535.48,2779.86 h60
  text "RoHS" at 12663.47,2779.86 h60
  text "OTHER" at 13307.87,2779.86 h60
  text "PER ORDER" at 13704.93,2779.86 h60
  text "4. LAYER TO LAYER REGISTRATION SHALL BE WITHIN +/-2 MIL." at 4632.59,2745.51 h60
  text "ALL BOARDS MUST MEET OR EXCEED UL94-V0 REQUIREMENTS." at 11388.51,2626.03 h60
  text "C" at 14411.01,2624.96 h70
  text "5. REFER IMPEDANCE TABLE FOR IMPEDANCE CONTROL TRACES ON LAYER 1 & 4" at 4632.59,2579.64 h60
  text "PCB MUST BEAR THE UL94V-0 UL REGISTERED MATERIAL ID NUMBER" at 11388.51,2509.97 h60
  text "6. ALL VIAS ARE TENTED ON BOTH SIDES UNLESS OTHERWISE SOLDER MASK OPENED IN GERBER." at 4632.59,2419.49 h60
  text "ADDITIONAL REQUIREMENTS:" at 11360.97,2340.54 h60
  text "MICROSECTION:" at 11435.74,2233.42 h60
  text "YES" at 12341.47,2233.42 h60
  text "REQUIRED" at 13202.97,2089.09 h60
  text "BARE BOARD ELEC. TEST:" at 11435.74,2086.23 h60
  text "NONE" at 12741.47,2086.23 h60
  text "X" at 13084.97,2086.23 h60
  text "PER ORDER" at 13794.97,2086.23 h60
  text "XX MIL VIAS REQUIRE NON-CONDUCTIVE FILL AND PLANARIZE" at 11619.51,1940.46 h59
  text "XX MIL VIAS REQUIRE CONDUCTIVE FILL AND PLANARIZE" at 11610.51,1781.46 h60
  text "OUTER XX MIL TRACES REQUIRE 50 OHM SINGLE-ENDED IMPEDANCE" at 11605.66,1638.57 h58
  text "LAYER 1 & 6 (INNER LAYERS) XX MIL WIDE, XX MIL SPACE / TRACES REQUIRE 100 OHM DIFFERENTIAL IMPEDANCE" at 11644.51,1388.46 h60
  text "PROJECT TITLE:" at 11371.01,763.96 h45
  text "C2000 XDS110 EMULATOR" at 11421.01,630.64 h70
  text "DESIGNED FOR:" at 11371.01,462.96 h45
  text ".PRJ_Customer" at 11421.01,322.96 h70
  text "D" at 14411.01,254.96 h70
  text "FILE NAME:" at 11371.01,162.96 h45
  text ".PCB_File_Name_No_Path" at 11421.01,42.96 h70
  text "Texas Instruments (TI) and/or its licensors do not warrant the accuracy or completeness of this specification" at 6401.51,-118.87 h45
  text "ENGINEER:" at 11371.01,-127.04 h45
  text "LAYOUT BY:" at 12876.01,-127.04 h45
  text "or any information contained therein. TI and/or its licensors do not warrant that this design will meet" at 6356.52,-231.54 h45
  text ".PCB_Layout" at 12926.51,-282.03 h70
  text "the specifications, will be suitable for your application or fit for any particular purpose, or will operate in" at 6356.52,-344.2 h45
  text ".Layer_Name" at 596.92,-407.66 h60
  text "ALTIUM DESIGNER VERSION:" at 12876.01,-437.04 h45
  text "an implementation. TI and/or its licensors do not warrant that the design is production worthy. You should" at 6356.52,-456.87 h45
  text "completely validate and test your design implementation to confirm the system functionality for your application." at 6401.51,-569.54 h45
  text ".print_Scale" at 11421.01,-570.36 h70
  text ".Application_BuildNumber" at 12926.51,-570.36 h70
  text "4" at 8290.75,-771.8 h70
  text "1" at 767.35,-777.04 h70
  text "2" at 3263.01,-777.04 h70
  text "3" at 5752.35,-777.04 h70
  text "5" at 10758.01,-777.04 h70
  text "6" at 13112.19,-787.39 h70
M11 Gerber Information:
  lines w10: -265.19,-445.49 6334.81,-445.49 ; -265.19,-242.15 6336.81,-242.15 ; -265.19,-38.82 -265.19,-648.82 3739.81,-648.82 6336.81,-648.82 6336.81,-38.82 -264.69,-38.82 -264.69,-648.82 1310.81,-648.82 ; 2199.81,-648.82 2199.81,-38.82 ; 3466.81,-242.15 3466.81,-38.82 ; 4306.81,-242.15 4306.81,-38.82 ; 4928.81,-655.32 4928.81,-452.49
  text "ALL ARTWORK VIEWED FROM TOP SIDE" at -201.69,-170.99 h60
  text "BOARD #:" at 2274.81,-170.99 h60
  text ".PRJ_Number" at 2820.31,-170.99 h60
  text "REV:" at 3664.81,-170.99 h60
  text ".PCB_Rev" at 3956.31,-170.99 h60
  text "SVN REV:" at 4502.81,-170.99 h60
  text ".VersionControl_RevNumber" at 5008.81,-170.99 h60
  text "LAYER NAME =" at -201.69,-373.81 h60
  text "TID #:" at 2274.81,-374.32 h60
  text ".TID" at 2820.31,-374.32 h60
  text "PLOT NAME =" at -201.69,-579.65 h60
  text ".plot_File_Name" at 603.81,-579.65 h60
  text "GENERATED    :" at 2276.81,-579.65 h60
  text ".Print_Date" at 3146.31,-579.65 h60
  text ".Print_Time" at 3875.31,-579.65 h60
  text "TEXAS INSTRUMENTS" at 5139.81,-579.65 h60
M12 Stackup:
  drawing of 349 lines, arcs and shapes, not listed
  text "NOTE :" at 6629.57,6355.46 h60
  text "1. THIS IS AN IMPEDANCE CONTROLLED BOARD." at 6979.49,6344.42 h60
  text "2. EXTERNAL LAYER CU THICKNESSES ARE FINISHED THICKNESS AFTER PLATING." at 6975,6215 h60
  text "6" at 6436.15,5337.79 h60
  text "IMPEDANCE TABLE :" at 5279.76,5322.41 h80
  text "LAYER" at 4820.02,5132.76 h70
  text "TRACE WIDTH" at 5107.23,5131.91 h70
  text "SPACING" at 5592.23,5131.91 h70
  text "IMPEDANCE +/- 10%" at 5927.23,5131.91 h70
  text "REFERENCE LAYER" at 6652.23,5131.91 h70
  text "TOP" at 4880.91,4960.93 h70
  text "5 MILS" at 5165.91,4955.93 h65
  text "-" at 5620.91,4955.93 h65
  text "50 OHM" at 6040.91,4955.93 h65
  text "LAYER-2 (GND LAYER)" at 6605.91,4955.93 h65
  text "4 MILS" at 5184.16,4782.05 h65
  text "10 MILS" at 5623.06,4782.05 h65
  text "100 OHM" at 6095.11,4782.05 h65
  text "LAYER-2 (GND LAYER)" at 6607.11,4773.73 h65
  text "TOP" at 4832.51,4763.37 h70
  text "4 MILS" at 5184.16,4591.73 h65
  text "TOP" at 4818.11,4587.73 h60
  text "90 OHM" at 6095.11,4587.73 h65
  text "LAYER-2 (GND LAYER)" at 6604.11,4587.73 h65
  text "6 MILS" at 5623.06,4584.73 h65
  text "-" at 5699.07,4410.6 h65
  text "5 MILS" at 5183.12,4404.81 h65
  text "LAYER-3" at 6779.22,4403.44 h65
  text "50 OHM" at 6094.07,4401.6 h65
  text "BOTTOM" at 4787.47,4383.66 h60
  text "4 MILS" at 5183.12,4228.81 h65
  text "10 MILS" at 5622.02,4228.81 h65
  text "LAYER-3" at 6779.22,4227.44 h65
  text "100 OHM" at 6094.07,4225.6 h65
  text "BOTTOM" at 4790.47,4207.66 h60
  text "4 MILS" at 5183.12,4057.58 h65
  text "6 MILS" at 5622.02,4057.58 h65
  text "LAYER-3" at 6779.22,4056.22 h65
  text "90 OHM" at 6094.07,4054.38 h65
  text "BOTTOM" at 4790.47,4036.44 h60
  text "LAYER STACK-UP :" at 4642.54,1991.74 h80
  text "Layer" at 4717.31,1793.68 h60
  text "Name" at 5127.22,1793.68 h60
  text "Material" at 6056.97,1793.68 h60
  text "Thickness" at 6916.73,1793.68 h60
  text "Constant" at 7566.57,1793.68 h60
  text "Board Layer Stack" at 8136.43,1793.68 h60
  text "Top Overlay" at 5127.22,1673.68 h60
  text "Top Solder" at 5127.22,1553.68 h60
  text "Solder Resist" at 6056.97,1553.68 h60
  text "1.00mil" at 6916.73,1553.68 h60
  text "3.5" at 7566.57,1553.68 h60
  text "1" at 4717.31,1433.68 h60
  text "Top Layer" at 5127.22,1433.68 h60
  text "1.97mil" at 6916.73,1433.68 h60
  text "Dielectric 2" at 5127.22,1313.68 h60
  text "FR-4" at 6056.97,1313.68 h60
  text "3.70mil" at 6916.73,1313.68 h60
  text "4.1" at 7566.57,1313.68 h60
  text "2" at 4717.31,1193.68 h60
  text "L2_GND" at 5127.22,1193.68 h60
  text "1.20mil" at 6916.73,1193.68 h60
  text "Dielectric 1" at 5127.22,1073.68 h60
  text "FR-4" at 6056.97,1073.68 h60
  text "45.00mil" at 6916.73,1073.68 h60
  text "4.8" at 7566.57,1073.68 h60
  text "3" at 4717.31,953.68 h60
  text "L3_PWR/SIG" at 5127.22,953.68 h60
  text "1.20mil" at 6916.73,953.68 h60
  text "Dielectric 3" at 5127.22,833.68 h60
  text "FR-4" at 6056.97,833.68 h60
  text "3.70mil" at 6916.73,833.68 h60
  text "4.1" at 7566.57,833.68 h60
  text "4" at 4717.31,713.68 h60
  text "Bottom Layer" at 5127.22,713.68 h60
  text "1.97mil" at 6916.73,713.68 h60
  text "Bottom Solder" at 5127.22,593.68 h60
  text "Solder Resist" at 6056.97,593.68 h60
  text "1.00mil" at 6916.73,593.68 h60
  text "3.5" at 7566.57,593.68 h60
  text "Bottom Overlay" at 5127.22,473.68 h60
  text ".Layer_Name" at 594.81,-408.82 h60
Drill Drawing:
  circle w10: c3447.25,7410.91 r20
  circle w10: c3447.25,7410.91 r33.33
  lines w10: 3413.92,6927.57 3480.59,6927.57 3480.59,6994.24 3413.92,6994.24 3413.92,6927.57 ; 3413.92,7077.57 3447.25,7094.24 3480.59,7077.57 3463.92,7110.91 3480.59,7144.24 3447.25,7127.57 3413.92,7144.24 3430.59,7110.91 3413.92,7077.57 ; 3413.92,7260.91 3447.25,7227.57 3480.59,7260.91 3447.25,7294.24 3413.92,7260.91 ; 3413.92,7527.57 3480.59,7527.57 3480.59,7594.24 3413.92,7594.24 3413.92,7527.57 ; 3413.92,7694.24 3430.59,7694.24 3430.59,7677.57 3463.92,7677.57 3463.92,7694.24 3480.59,7694.24 3480.59,7727.57 3463.92,7727.57 3463.92,7744.24 3430.59,7744.24 3430.59,7727.57 3413.92,7727.57 3413.92,7694.24 ; 3413.92,7844.24 3430.59,7844.24 3447.25,7827.57 3463.92,7844.24 3480.59,7844.24 3463.92,7860.91 3480.59,7877.57 3463.92,7877.57 3447.25,7894.24 3430.59,7877.57 3413.92,7877.57 3430.59,7860.91 3413.92,7844.24 ; 3413.92,8044.24 3480.59,8044.24 3447.25,7977.57 3413.92,8044.24 ; 3413.92,8127.57 3413.92,8144.24 3430.59,8160.91 3413.92,8177.57 3413.92,8194.24 3430.59,8194.24 3447.25,8177.57 3463.92,8194.24 3480.59,8194.24 3480.59,8177.57 3463.92,8160.91 3480.59,8144.24 3480.59,8127.57 3463.92,8127.57 3447.25,8144.24 3430.59,8127.57 3413.92,8127.57 ; 3427.25,6940.91 3467.25,6940.91 3467.25,6980.91 3427.25,6980.91 3427.25,6940.91
  lines w15: 3354.13,6882.57 11317.88,6882.57 ; 3354.13,8232.57 11317.88,8232.57 ; 3905.01,6732.57 3905.01,8382.57 ; 4504.85,6732.57 4504.85,8382.57 ; 5654.51,6732.57 5654.51,8382.57 ; 6160.39,6732.57 6160.39,8382.57 ; 7659.94,6732.57 7659.94,8382.57 ; 8749.62,6732.57 8749.62,8382.57 ; 10011.25,6732.57 10011.25,8382.57 ; 3354.13,6732.57 11317.88,6732.57 11317.88,8382.57 3354.13,8382.57 3354.13,6732.57
  text "Symbol" at 3444.13,8277.57 h72
  text "Count" at 3950.01,8277.57 h72
  text "Hole Size" at 4549.85,8277.57 h72
  text "Plated" at 5699.51,8277.57 h72
  text "Drill Layer Pair" at 6205.39,8277.57 h72
  text "Hole Length" at 7704.94,8277.57 h72
  text "Hole Tolerance(+)" at 8794.62,8277.57 h72
  text "Hole Tolerance(-)" at 10056.25,8277.57 h72
  text "219" at 3950.01,8127.57 h60
  text "8.00mil (0.203mm)" at 4549.85,8127.57 h60
  text "PTH" at 5699.51,8127.57 h60
  text "Top Layer - Bottom Layer" at 6205.39,8127.57 h60
  text "-" at 7704.94,8127.57 h60
  text "3.00mil (0.076mm)" at 8794.62,8127.57 h60
  text "3.00mil (0.076mm)" at 10056.25,8127.57 h60
  text "14" at 3950.01,7977.57 h60
  text "15.75mil (0.400mm)" at 4549.85,7977.57 h60
  text "PTH" at 5699.51,7977.57 h60
  text "Top Layer - Bottom Layer" at 6205.39,7977.57 h60
  text "-" at 7704.94,7977.57 h60
  text "3.00mil (0.076mm)" at 8794.62,7977.57 h60
  text "3.00mil (0.076mm)" at 10056.25,7977.57 h60
  text "4" at 3950.01,7827.57 h60
  text "23.62mil (0.600mm)" at 4549.85,7827.57 h60
  text "PTH" at 5699.51,7827.57 h60
  text "Top Layer - Bottom Layer" at 6205.39,7827.57 h60
  text "47.24mil (1.200mm)" at 7704.94,7827.57 h60
  text "3.00mil (0.076mm)" at 8794.62,7827.57 h60
  text "3.00mil (0.076mm)" at 10056.25,7827.57 h60
  text "3" at 3950.01,7677.57 h60
  text "37.99mil (0.965mm)" at 4549.85,7677.57 h60
  text "PTH" at 5699.51,7677.57 h60
  text "Top Layer - Bottom Layer" at 6205.39,7677.57 h60
  text "-" at 7704.94,7677.57 h60
  text "3.00mil (0.076mm)" at 8794.62,7677.57 h60
  text "3.00mil (0.076mm)" at 10056.25,7677.57 h60
  text "5" at 3950.01,7527.57 h60
  text "39.37mil (1.000mm)" at 4549.85,7527.57 h60
  text "PTH" at 5699.51,7527.57 h60
  text "Top Layer - Bottom Layer" at 6205.39,7527.57 h60
  text "-" at 7704.94,7527.57 h60
  text "3.00mil (0.076mm)" at 8794.62,7527.57 h60
  text "3.00mil (0.076mm)" at 10056.25,7527.57 h60
  text "16" at 3950.01,7377.57 h60
  text "40.95mil (1.040mm)" at 4549.85,7377.57 h60
  text "PTH" at 5699.51,7377.57 h60
  text "Top Layer - Bottom Layer" at 6205.39,7377.57 h60
  text "-" at 7704.94,7377.57 h60
  text "3.00mil (0.076mm)" at 8794.62,7377.57 h60
  text "3.00mil (0.076mm)" at 10056.25,7377.57 h60
  text "108" at 3950.01,7227.57 h60
  text "32.00mil (0.813mm)" at 4549.85,7227.57 h60
  text "NPTH" at 5699.51,7227.57 h60
  text "Top Layer - Bottom Layer" at 6205.39,7227.57 h60
  text "-" at 7704.94,7227.57 h60
  text "3.00mil (0.076mm)" at 8794.62,7227.57 h60
  text "3.00mil (0.076mm)" at 10056.25,7227.57 h60
  text "2" at 3950.01,7077.57 h60
  text "45.28mil (1.150mm)" at 4549.85,7077.57 h60
  text "NPTH" at 5699.51,7077.57 h60
  text "Top Layer - Bottom Layer" at 6205.39,7077.57 h60
  text "-" at 7704.94,7077.57 h60
  text "3.00mil (0.076mm)" at 8794.62,7077.57 h60
  text "3.00mil (0.076mm)" at 10056.25,7077.57 h60
  text "4" at 3950.01,6927.57 h60
  text "160.00mil (4.064mm)" at 4549.85,6927.57 h60
  text "NPTH" at 5699.51,6927.57 h60
  text "Top Layer - Bottom Layer" at 6205.39,6927.57 h60
  text "-" at 7704.94,6927.57 h60
  text "3.00mil (0.076mm)" at 8794.62,6927.57 h60
  text "3.00mil (0.076mm)" at 10056.25,6927.57 h60
  text "375 Total" at 3950.01,6777.57 h60
  text "Slot definitions :" at 3444.13,6632.6 h60
  text "Routed Path Length" at 4476.82,6632.6 h60
  text "= Calculated from tool start centre position to tool end centre position." at 5579.49,6632.6 h60
  text "Hole Length" at 4476.82,6532.63 h60
  text "= Routed Path Length + Tool Size = Slot length as defined in the PCB layout" at 5169.62,6532.63 h60

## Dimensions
4238.97,6500.57 to 0,6500.57 on M2 Board Dimensions
4238.97,6500.57 to 4238.97,0 on M2 Board Dimensions
279.81,1691.18 to 3369.81,1976.18 on M2 Board Dimensions
274.81,3391.18 to 279.81,1691.18 on M2 Board Dimensions
3369.81,3111.18 to 3369.81,1976.18 on M2 Board Dimensions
